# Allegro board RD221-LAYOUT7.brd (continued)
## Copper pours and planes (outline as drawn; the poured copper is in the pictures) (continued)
VOUT on TOP: 46.95,22 46.83,22.03 46.73,22.12 46.7,22.25 46.7,28.55 46.73,28.68 46.83,28.77 46.95,28.8 53.05,28.8 53.17,28.77 53.27,28.68 53.3,28.55 53.3,22.25 53.27,22.12 53.17,22.03 53.05,22
VOUT on TOP: outline of 200 points within 29.8,20.1 65,69.45
VOUT on TOP: 26.95,22 26.82,22.03 26.73,22.12 26.7,22.25 26.7,28.55 26.73,28.68 26.82,28.77 26.95,28.8 33.05,28.8 33.17,28.77 33.27,28.68 33.3,28.55 33.3,22.25 33.27,22.12 33.17,22.03 33.05,22
VOUT on TOP: 36.95,22 36.83,22.03 36.73,22.12 36.7,22.25 36.7,28.55 36.73,28.68 36.83,28.77 36.95,28.8 43.05,28.8 43.17,28.77 43.27,28.68 43.3,28.55 43.3,22.25 43.27,22.12 43.17,22.03 43.05,22
VOUT on TOP: 56.95,22 56.83,22.03 56.73,22.12 56.7,22.25 56.7,28.55 56.73,28.68 56.83,28.77 56.95,28.8 63.05,28.8 63.17,28.77 63.27,28.68 63.3,28.55 63.3,22.25 63.27,22.12 63.17,22.03 63.05,22
VOUT on BOTTOM: 64,22.25 63.93,22.07 63.75,22 26.85,22 26.67,22.07 26.6,22.25 26.6,30.5 26.62,30.59 26.67,30.67 27.93,31.93 28.01,31.98 28.1,32 35.7,32 35.79,32.02 35.87,32.07 38.93,35.13 38.99,35.24 39,35.3 39,57.1 38.97,57.22 38.93,57.27 34.87,61.33 34.76,61.39 34.7,61.4 31.5,61.4 31.38,61.37 31.33,61.33 28.07,58.07 27.99,58.02 27.9,58 26.1,58 26.01,58.02 25.93,58.07 25.07,58.93 25.02,59.01 25,59.1 25,61.3 25.02,61.39 25.07,61.47 29.73,66.13 29.78,66.21 29.8,66.3 29.8,69.38 29.82,69.43 29.87,69.45 37.9,69.45 37.99,69.43 38.07,69.38 46.93,60.52 46.98,60.44 47,60.35 47,33.3 47.02,33.21 47.07,33.13 48.13,32.07 48.21,32.02 48.3,32 59.9,32 59.99,31.98 60.07,31.93 63.93,28.07 63.98,27.99 64,27.9 ; 13 cut-outs
VP_4R8 on TOP: 40.27,55.33 40.19,55.38 40.1,55.4 33.45,55.4 33.27,55.47 33.2,55.65 33.2,57.95 33.27,58.13 33.45,58.2 41.7,58.2 41.79,58.18 41.87,58.13 43.93,56.07 44.04,56.01 44.1,56 56.95,56 57.08,55.97 57.17,55.88 57.2,55.75 57.2,53.25 57.17,53.12 57.08,53.03 56.95,53 42.7,53 42.64,53.01 42.53,53.07
VP_4R8 on TOP: 13.8,75.34 13.81,75.4 13.84,75.44 14.16,75.76 14.2,75.79 14.26,75.8 15.74,75.8 15.84,75.76 16.16,75.44 16.2,75.34 16.2,73.45 16.16,73.34 16.05,73.3 13.95,73.3 13.84,73.34 13.8,73.45 ; 2 cut-outs
VP_4R8 on TOP: 20.4,83.87 20.38,83.82 20.33,83.8 16.45,83.8 16.27,83.73 16.2,83.55 16.2,81.9 16.18,81.81 16.13,81.73 15.87,81.47 15.79,81.42 15.7,81.4 14.85,81.4 14.72,81.37 14.63,81.28 14.6,81.15 14.6,79.94 14.58,79.89 14.53,79.87 14.22,79.87 14.09,79.83 13.99,79.73 13.95,79.59 13.95,79.1 13.99,78.96 14.09,78.86 14.22,78.83 14.53,78.83 14.58,78.8 14.6,78.75 14.6,77.87 14.58,77.81 14.53,77.79 14.46,77.79 14.3,77.73 14.24,77.57 14.24,77.33 14.22,77.27 14.16,77.25 13.55,77.25 13.44,77.29 13.4,77.4 13.4,86.43 13.42,86.48 13.47,86.5 15.95,86.5 16.13,86.43 16.2,86.25 16.2,84.35 16.27,84.17 16.45,84.1 20.33,84.1 20.38,84.08 20.4,84.03 ; 3 cut-outs
VP_4R8 on BOTTOM: outline of 203 points within 52.8,17.6 80.4,56 ; 3 cut-outs
VP_4R8 on BOTTOM: outline of 272 points within 6.8,17.6 35,84.4 ; 8 cut-outs

Small or netless copper shapes (teardrops, artwork), in the pictures only: 249 on TOP, 18 on BOTTOM

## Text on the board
Ref Des/Silkscreen Top: 3 | 1 | 4 | 2 | 1A | 6A | 6 | 2A | 16 | 16A
SYMBOL-1-TOP: SW4 | Q12 | C11 | R10 | IC1 | C18 | C17 | CN3 | R17 | R18 | C2 | IC3 | C14 | IC11 | LED1 | C1 | IC2 | Q5 | Q10 | TP1 | TP4 | TP3 | SW3 | Q13 | R16 | R9 | C10 | C24 | C12 | IC9 | Q11 | CN1 | C23 | IC7 | C9 | CN2 | C22 | Q9 | IC6 | C4 | SW2 | C6 | TP2 | R3 | R20 | Q7 | IC4 | C3 | Q8 | C13 | SW6 | IC10 | SW1 | R14 | R4 | C5 | Q6 | SW5 | R13 | C19 | R19 | R12 | C15 | D4 | Q3 | Q4 | IC8 | R5 | Q1 | Q2 | C21 | D3 | C16 | R11 | R8 | CN5 | CN4 | R2 | R7 | C8 | D2 | R1 | IC5 | C20 | D1 | C7 | R6 | 3 | 1 | 2A | 2 | 1A | 4 | 16A | 16 | 6A | 6 | Multiplexer | Base Board
SYMBOL-2-TOP: LOAD-D | setting | RD221 | Gate Driver IC for | Common Drain MOSFET | MUX 1/2/3/5/6 | 3 | 1 | 2 | 4 | 16 | 6 | CN3 | R13 | SW5 | SW4 | GND | C11 | IC3 | C18 | C17 | C2 | R17 | FLAG | R10 | IC1 | IC11 | C14 | IC2 | C1 | IC8 | Q5 | LED1 | VINA | VOUT | TP1 | TP4 | TP3 | LOADD | CN1 | SW3 | R16 | Q13 | C10 | R9 | C12 | IC9 | C24 | Q11 | VINB | LOADC | C9 | C23 | IC7 | VDD | Q9 | C22 | SW2 | C4 | IC6 | LOADB | C6 | TP2 | Q7 | R20 | R3 | C3 | IC4 | Q8 | LOADA | R14 | IC10 | C13 | SW6 | SW1 | IC5 | CN2 | R4 | C5 | Q6 | C19 | R19 | Q12 | R12 | C15 | Q4 | R18 | D4 | Q3 | R5 | Q2 | C21 | Q1 | D3 | R11 | C16 | Q10 | R8 | CN5 | CN4 | R2 | C8 | R7 | D2 | R1 | C20 | C7 | D1 | R6 | DC | PULSE | BBM | Base Board | Multiplexer | MBB
